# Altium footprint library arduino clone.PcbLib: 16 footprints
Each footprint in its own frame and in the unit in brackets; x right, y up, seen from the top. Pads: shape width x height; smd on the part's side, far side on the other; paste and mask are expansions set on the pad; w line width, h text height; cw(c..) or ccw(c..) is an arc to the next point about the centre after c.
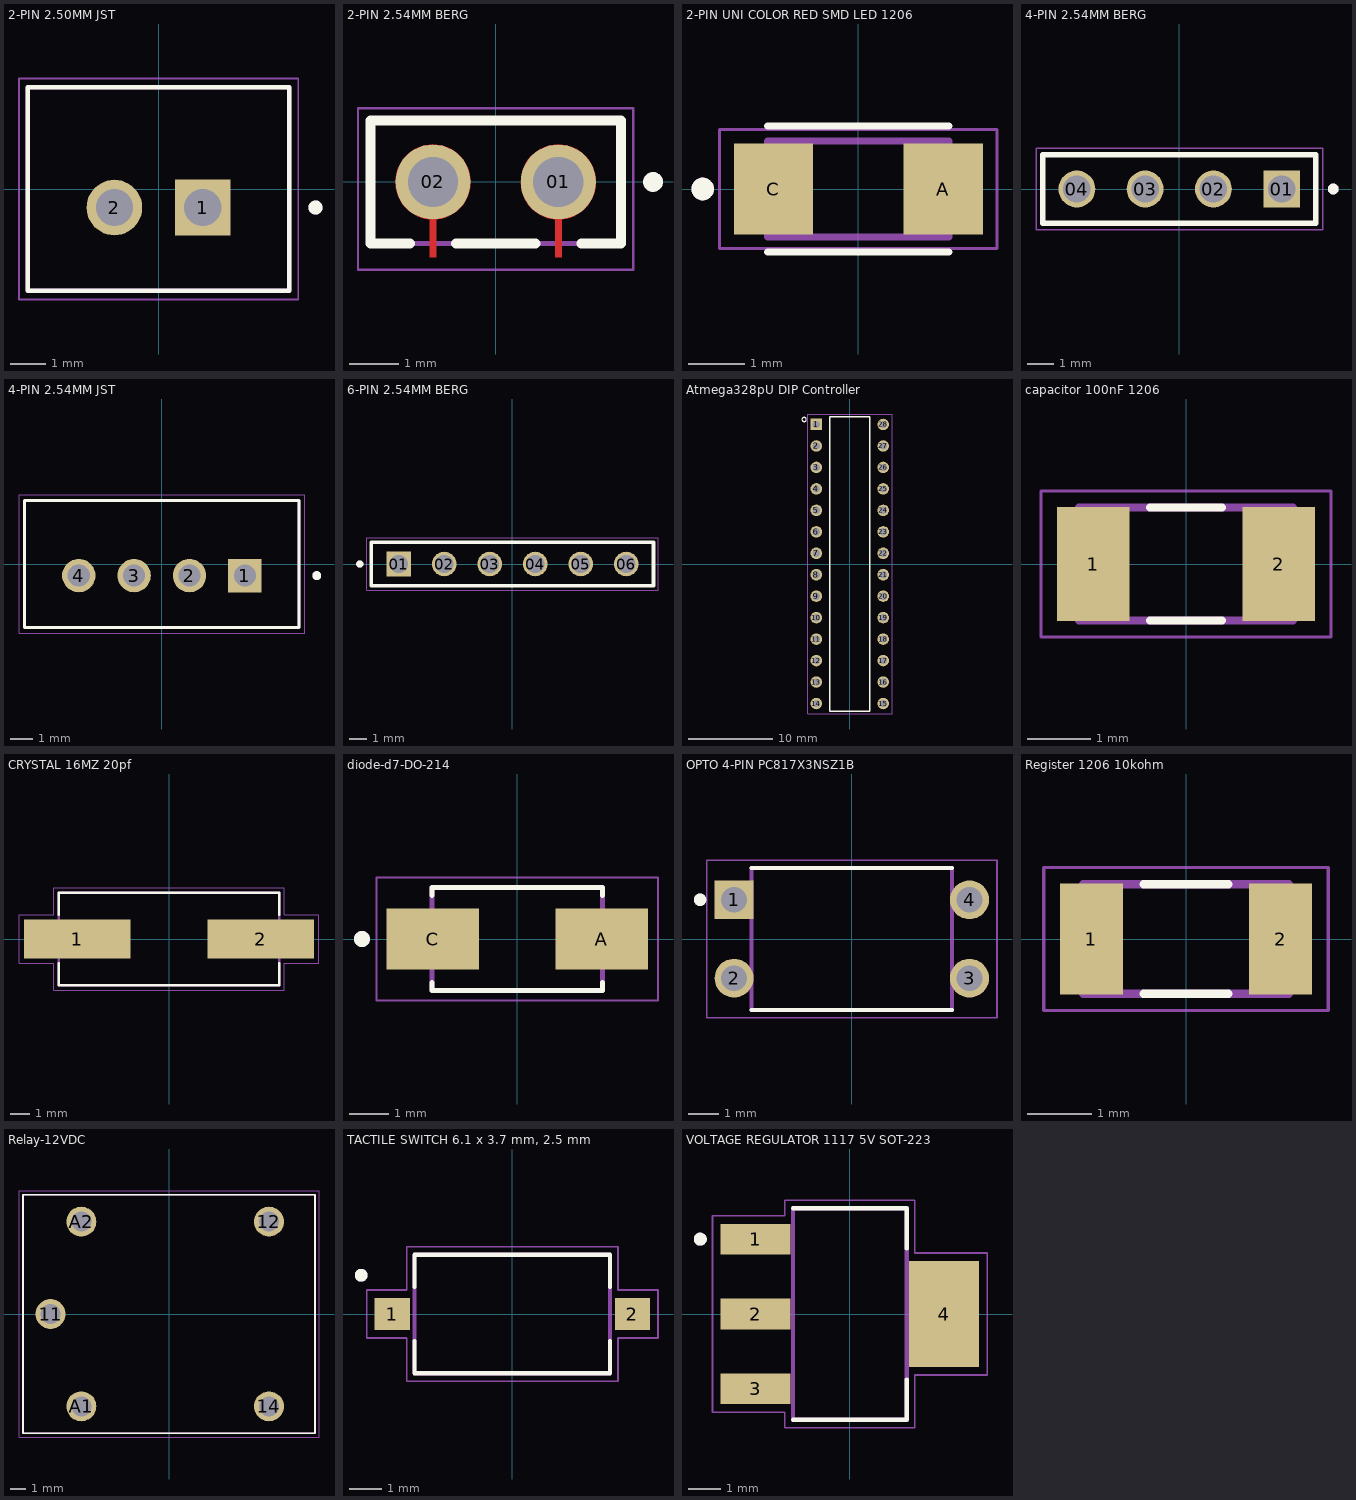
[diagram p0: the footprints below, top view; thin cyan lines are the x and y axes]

## 2-PIN 2.50MM JST [mm]
height 7
pads (2):
  rect 1.575x1.575 / inner round 1.575 / far side rect 1.575x1.575 hole 1.05: 1(1.25,-0.525)
  round 1.575 hole 1.05: 2(-1.25,-0.525)
Top Layer:
  text "OPTO 4-PIN PC817X3NSZ1B" at -7.874,-4.826 h1.52
Top Overlay:
  circle w0.2: c4.44,-0.525 r0.1
  lines w0.127: -3.7,-2.875 3.7,-2.875 3.7,2.875 -3.7,2.875 -3.7,-2.875
Mechanical 13:
  circle w0.2: c4.44,-0.525 r0.1
  lines w0.127: -3.7,-2.875 3.7,-2.875 3.7,2.875 -3.7,2.875 -3.7,-2.875
Mechanical 15:
  lines w0.05: -3.95,-3.125 -3.95,3.125 3.95,3.125 3.95,-3.125 -3.95,-3.125
3D body "step_temp.STEP": height 7, standoff -3.4, extent -3.7,-2.875 3.7,2.875

## 2-PIN 2.54MM BERG [mm] "SAMTEC_MTLW-102-08-L-S-300"
pads (2):
  round 1.52 hole 1.02: 01(1.27,0) 02(-1.27,0)
Top Layer:
  region: -1.191,0.756 -1.112,0.743 -1.035,0.723 -0.961,0.694 -0.89,0.658 -0.823,0.615 -0.761,0.565 -0.705,0.509 -0.655,0.447 -0.612,0.38 -0.576,0.309 -0.547,0.235 -0.527,0.158 -0.514,0.079 -0.51,0 -0.511,-0.038 -0.514,-0.076 -0.518,-0.113 -0.525,-0.151 -0.533,-0.187 -0.543,-0.224 -0.555,-0.259 -0.569,-0.294 -0.584,-0.329 -0.601,-0.363 -0.62,-0.395 -0.64,-0.427 -0.662,-0.458 -0.685,-0.487 -0.71,-0.516 -0.736,-0.543 -0.764,-0.569 -0.793,-0.593 -0.822,-0.616 -0.853,-0.638 -0.885,-0.658 -0.918,-0.676 -0.952,-0.692 -0.987,-0.707 -1.022,-0.721 -1.058,-0.732 -1.094,-0.742 -1.131,-0.75 -1.168,-0.756 -1.205,-0.76 -1.205,-1.53 -1.335,-1.53 -1.335,-0.76 -1.372,-0.756 -1.409,-0.75 -1.446,-0.742 -1.482,-0.732 -1.518,-0.721 -1.553,-0.707 -1.588,-0.692 -1.622,-0.676 -1.655,-0.658 -1.687,-0.638 -1.718,-0.616 -1.747,-0.593 -1.776,-0.569 -1.804,-0.543 -1.83,-0.516 -1.855,-0.487 -1.878,-0.458 -1.9,-0.427 -1.92,-0.395 -1.939,-0.363 -1.956,-0.329 -1.971,-0.294 -1.985,-0.259 -1.997,-0.224 -2.007,-0.187 -2.015,-0.151 -2.022,-0.113 -2.026,-0.076 -2.029,-0.038 -2.03,0 -2.026,0.079 -2.013,0.158 -1.993,0.235 -1.964,0.309 -1.928,0.38 -1.885,0.447 -1.835,0.509 -1.779,0.565 -1.717,0.615 -1.65,0.658 -1.579,0.694 -1.505,0.723 -1.428,0.743 -1.349,0.756 -1.27,0.76
  region: 1.349,0.756 1.428,0.743 1.505,0.723 1.579,0.694 1.65,0.658 1.717,0.615 1.779,0.565 1.835,0.509 1.885,0.447 1.928,0.38 1.964,0.309 1.993,0.235 2.013,0.158 2.026,0.079 2.03,0 2.029,-0.038 2.026,-0.076 2.022,-0.113 2.015,-0.151 2.007,-0.187 1.997,-0.224 1.985,-0.259 1.971,-0.294 1.956,-0.329 1.939,-0.363 1.92,-0.395 1.9,-0.427 1.878,-0.458 1.855,-0.487 1.83,-0.516 1.804,-0.543 1.776,-0.569 1.747,-0.593 1.718,-0.616 1.687,-0.638 1.655,-0.658 1.622,-0.676 1.588,-0.692 1.553,-0.707 1.518,-0.721 1.482,-0.732 1.446,-0.742 1.409,-0.75 1.372,-0.756 1.335,-0.76 1.335,-1.53 1.205,-1.53 1.205,-0.76 1.168,-0.756 1.131,-0.75 1.094,-0.742 1.058,-0.732 1.022,-0.721 0.987,-0.707 0.952,-0.692 0.918,-0.676 0.885,-0.658 0.853,-0.638 0.822,-0.616 0.793,-0.593 0.764,-0.569 0.736,-0.543 0.71,-0.516 0.685,-0.487 0.662,-0.458 0.64,-0.427 0.62,-0.395 0.601,-0.363 0.584,-0.329 0.569,-0.294 0.555,-0.259 0.543,-0.224 0.533,-0.187 0.525,-0.151 0.518,-0.113 0.514,-0.076 0.511,-0.038 0.51,0 0.514,0.079 0.527,0.158 0.547,0.235 0.576,0.309 0.612,0.38 0.655,0.447 0.705,0.509 0.761,0.565 0.823,0.615 0.89,0.658 0.961,0.694 1.035,0.723 1.112,0.743 1.191,0.756 1.27,0.76
Top Overlay:
  circle w0.2: c3.19,0 r0.1
  lines w0.2: -1.735,-1.245 -2.54,-1.245 -2.54,1.245 2.54,1.245 2.54,-1.245 1.735,-1.245 ; -0.805,-1.245 0.805,-1.245
Top Paste:
  region: -0.19,-0.455 -0.65,-0.455 -1.015,-0.77 -1.015,-1.53 -1.525,-1.53 -1.525,-0.77 -1.89,-0.455 -2.35,-0.455 -2.35,1.085 -0.19,1.085
  region: 2.35,-0.455 1.89,-0.455 1.525,-0.77 1.525,-1.53 1.015,-1.53 1.015,-0.77 0.65,-0.455 0.19,-0.455 0.19,1.085 2.35,1.085
Top Solder:
  drawing of 2 lines, arcs and shapes, not listed
Mechanical 13:
  circle w0.2: c3.19,0 r0.1
  lines w0.1: -2.54,-1.245 2.54,-1.245 2.54,1.245 -2.54,1.245 -2.54,-1.245
Mechanical 15:
  lines w0.05: -2.79,-1.78 2.79,-1.78 2.79,1.495 -2.79,1.495 -2.79,-1.78

## 2-PIN UNI COLOR RED SMD LED 1206 [mm] "LED_BR1102W-TR"
pads (2):
  rect 1.4x1.6 smd: A(1.5,0) C(-1.5,0)
Top Overlay:
  circle w0.2: c-2.75,0 r0.1
  lines w0.127: -1.6,-1.114 1.6,-1.114 ; -1.6,1.114 1.6,1.114
Mechanical 13:
  circle w0.2: c-2.75,0 r0.1
  lines w0.127: -1.6,-0.85 1.6,-0.85 1.6,0.85 -1.6,0.85 -1.6,-0.85
Mechanical 15:
  lines w0.05: -2.45,-1.05 2.45,-1.05 2.45,1.05 -2.45,1.05 -2.45,-1.05

## 4-PIN 2.54MM BERG [mm] "SAMTEC_MTSW-104-22-S-S-415"
pads (4):
  rect 1.37x1.37 / inner round 1.37 / far side rect 1.37x1.37 hole 1.02: 01(3.81,0)
  round 1.37 hole 1.02: 02(1.27,0) 03(-1.27,0) 04(-3.81,0)
Top Overlay:
  circle w0.2: c5.73,0 r0.1
  lines w0.2: -5.08,-1.27 -5.08,1.27 5.08,1.27 5.08,-1.27 -5.08,-1.27
Mechanical 13:
  circle w0.2: c5.73,0 r0.1
  lines w0.1: -5.08,-1.27 -5.08,1.27 ; -5.08,-1.27 5.08,-1.27 ; -5.08,-1.27 -5.08,1.27 ; -5.08,1.27 5.08,1.27 ; -5.08,1.27 5.08,1.27 ; 5.08,-1.27 5.08,1.27 ; 5.08,-1.27 5.08,1.27
Mechanical 15:
  lines w0.05: -5.33,-1.52 -5.33,1.52 5.33,1.52 5.33,-1.52 -5.33,-1.52

## 4-PIN 2.54MM JST [mm] "JST_B4B-XH-A"
height 7
pads (4):
  rect 1.508x1.508 / inner round 1.508 / far side rect 1.508x1.508 hole 1: 1(3.75,-0.525)
  round 1.508 hole 1: 2(1.25,-0.525) 3(-1.25,-0.525) 4(-3.75,-0.525)
Top Overlay:
  circle w0.2: c7,-0.525 r0.1
  lines w0.127: -6.2,-2.875 6.2,-2.875 6.2,2.875 -6.2,2.875 -6.2,-2.875
Mechanical 13:
  circle w0.2: c7,-0.525 r0.1
  lines w0.127: -6.2,-2.875 6.2,-2.875 6.2,2.875 -6.2,2.875 -6.2,-2.875
Mechanical 15:
  lines w0.05: -6.45,-3.125 6.45,-3.125 6.45,3.125 -6.45,3.125 -6.45,-3.125
3D body "step_temp.STEP": height 7, standoff -3.4, extent -6.2,-2.875 6.2,2.875

## 6-PIN 2.54MM BERG [mm] "berg-connector-6pin-2.54mm"
pads (6):
  rect 1.37x1.37 / inner round 1.37 / far side rect 1.37x1.37 hole 1.02: 01(-6.35,0)
  round 1.37 hole 1.02: 02(-3.81,0) 03(-1.27,0) 04(1.27,0) 05(3.81,0) 06(6.35,0)
Top Overlay:
  circle w0.2: c-8.525,0 r0.1
  lines w0.2: -7.875,-1.205 7.875,-1.205 7.875,1.205 -7.875,1.205 -7.875,-1.205
Mechanical 13:
  circle w0.2: c-8.525,0 r0.1
  lines w0.1: -7.875,-1.205 -7.875,1.205 ; -7.875,-1.205 7.875,-1.205 ; -7.875,-1.205 -7.875,1.205 ; -7.875,1.205 7.875,1.205 ; -7.875,1.205 7.875,1.205 ; 7.875,-1.205 7.875,1.205 ; 7.875,-1.205 7.875,1.205
Mechanical 15:
  lines w0.05: -8.125,-1.455 8.125,-1.455 8.125,1.455 -8.125,1.455 -8.125,-1.455

## Atmega328pU DIP Controller [mm] "Atmega328pU DIP"
pads (28):
  rect 1.358x1.358 hole 0.85: 1(-3.96,16.51)
  round 1.358 hole 0.85: 2(-3.96,13.97) 3(-3.96,11.43) 4(-3.96,8.89) 5(-3.96,6.35) 6(-3.96,3.81) 7(-3.96,1.27) 8(-3.96,-1.27) 9(-3.96,-3.81) 10(-3.96,-6.35) 11(-3.96,-8.89) 12(-3.96,-11.43) 13(-3.96,-13.97) 14(-3.96,-16.51) 15(3.96,-16.51) 16(3.96,-13.97) 17(3.96,-11.43) 18(3.96,-8.89) 19(3.96,-6.35) 20(3.96,-3.81) 21(3.96,-1.27) 22(3.96,1.27) 23(3.96,3.81) 24(3.96,6.35) 25(3.96,8.89) 26(3.96,11.43) 27(3.96,13.97) 28(3.96,16.51)
Top Overlay:
  circle w0: c-5.4,17.1 r0.254
  lines w0.152: -2.38,-17.4 -2.38,17.4 2.38,17.4 2.38,-17.4 -2.38,-17.4
Mechanical 15:
  lines w0.05: -5,-17.75 5,-17.75 5,17.75 -5,17.75 -5,-17.75

## capacitor 100nF 1206 [mm] "capacitor 100nF 1206"
pads (2):
  rect 1.16x1.82 smd: 1(-1.475,0) 2(1.475,0)
Top Overlay:
  lines w0.127: -0.57,-0.9 0.57,-0.9 ; -0.57,0.9 0.57,0.9
Mechanical 13:
  lines w0.127: -1.7,-0.9 -1.7,0.9 1.7,0.9 1.7,-0.9 -1.7,-0.9
Mechanical 15:
  lines w0.05: -2.308,-1.158 -2.308,1.158 2.308,1.158 2.308,-1.158 -2.308,-1.158

## CRYSTAL 16MZ 20pf [mm] "XTAL_ECS-160-20-5PX-TR"
pads (2):
  rect 5.5x2 smd: 1(-4.75,0) 2(4.75,0)
Top Overlay:
  lines w0.127: -5.7,-1.254 -5.7,-2.4 5.7,-2.4 5.7,-1.254 ; -5.7,1.254 -5.7,2.4 5.7,2.4 5.7,1.254
Mechanical 13:
  lines w0.127: -5.7,-2.4 -5.7,2.4 5.7,2.4 5.7,-2.4 -5.7,-2.4
Mechanical 15:
  lines w0.05: -7.75,-1.25 -5.95,-1.25 -5.95,-2.65 5.95,-2.65 5.95,-1.25 7.75,-1.25 7.75,1.25 5.95,1.25 5.95,2.65 -5.95,2.65 -5.95,1.25 -7.75,1.25 -7.75,-1.25
3D body "step_temp.STEP": height 3.2, standoff 0, extent -6.6,-2.4 6.6,2.4

## diode-d7-DO-214 [mm] "diode-d7-DO-214"
height 2.4
pads (2):
  rect 2.33x1.55 smd: A(2.135,0) C(-2.135,0)
Top Overlay:
  circle w0.2: c-3.919,0 r0.1
  lines w0.127: -2.15,-1.095 -2.15,-1.302 2.15,-1.302 2.15,-1.095 ; -2.15,1.095 -2.15,1.302 2.15,1.302 2.15,1.095
Mechanical 13:
  circle w0.2: c-3.919,0 r0.1
  lines w0.127: -2.15,-1.302 -2.15,1.302 2.15,1.302 2.15,-1.302 -2.15,-1.302
Mechanical 15:
  lines w0.05: -3.55,-1.552 -3.55,1.552 3.55,1.552 3.55,-1.552 -3.55,-1.552
3D body "step_temp.STEP": height 2.4, standoff 0, extent -2.598,-1.302 2.598,1.302

## OPTO 4-PIN PC817X3NSZ1B [mm] "DIP762W50P254L495H455Q4"
height 4.55
pads (4):
  rect 1.26x1.26 / inner round 1.26 / far side rect 1.26x1.26 hole 0.84: 1(-3.81,1.27)
  round 1.26 hole 0.84: 2(-3.81,-1.27) 3(3.81,-1.27) 4(3.81,1.27)
Top Overlay:
  circle w0.2: c-4.91,1.27 r0.1
  lines w0.127: -3.25,-2.3 3.25,-2.3 ; -3.25,2.3 3.25,2.3
Mechanical 13:
  circle w0.2: c-4.91,1.27 r0.1
  lines w0.127: -3.25,-2.3 -3.25,2.3 3.25,2.3 3.25,-2.3 -3.25,-2.3
Mechanical 15:
  lines w0.05: -4.7,-2.55 -4.7,2.55 4.7,2.55 4.7,-2.55 -4.7,-2.55
3D body "step_temp.STEP": height 4.55, standoff -3.6, extent -3.935,-2.3 3.935,2.3

## PCBComponent_1 [mm]

## Register 1206 10kohm [mm] "Register RESC3015X65N"
pads (2):
  rect 0.98x1.72 smd: 1(-1.47,0) 2(1.47,0)
Top Overlay:
  lines w0.127: -0.66,-0.85 0.66,-0.85 ; -0.66,0.85 0.66,0.85
Mechanical 13:
  lines w0.127: -1.6,-0.85 1.6,-0.85 1.6,0.85 -1.6,0.85 -1.6,-0.85
Mechanical 15:
  lines w0.05: -2.21,-1.11 2.21,-1.11 2.21,1.11 -2.21,1.11 -2.21,-1.11

## Relay-12VDC [mm] "RELAY_833H-1C-S-12VDC"
height 15.5
pads (5):
  round 1.95 hole 1.3: 11(-7.7,0) 12(6.5,6) 14(6.5,-6) A1(-5.7,-6) A2(-5.7,6)
Top Overlay:
  lines w0.127: -9.5,-7.75 -9.5,7.75 9.5,7.75 9.5,-7.75 -9.5,-7.75
Mechanical 13:
  lines w0.127: -9.5,-7.75 -9.5,7.75 9.5,7.75 9.5,-7.75 -9.5,-7.75
Mechanical 15:
  lines w0.05: -9.75,-8 -9.75,8 9.75,8 9.75,-8 -9.75,-8

## TACTILE SWITCH 6.1 x 3.7 mm, 2.5 mm [mm] "PUSHBUTTON_SMD_6.1 x 3.7 mm, 2.5 mm"
height 2.5
pads (2):
  rect 1.1x1 smd: 1(-3.75,0) 2(3.75,0)
Top Overlay:
  circle w0.2: c-4.72,1.21 r0.1
  lines w0.127: -3.05,-0.85 -3.05,-1.85 3.05,-1.85 3.05,-0.85 ; -3.05,0.85 -3.05,1.85 3.05,1.85 3.05,0.85
Mechanical 13:
  circle w0.2: c-4.72,1.21 r0.1
  lines w0.127: -3.05,-1.85 -3.05,1.85 3.05,1.85 3.05,-1.85 -3.05,-1.85
Mechanical 15:
  lines w0.05: -4.55,-0.75 -3.3,-0.75 -3.3,-2.1 3.3,-2.1 3.3,-0.75 4.55,-0.75 4.55,0.75 3.3,0.75 3.3,2.1 -3.3,2.1 -3.3,0.75 -4.55,0.75 -4.55,-0.75
3D body "step_temp.STEP": height 2.5, standoff -0.05, extent -4.05,-1.85 4.05,1.85

## VOLTAGE REGULATOR 1117 5V SOT-223 [mm] "SOT230P700X180-4N"
pads (4):
  rect 2.15x0.95 smd: 1(-2.9,2.3) 2(-2.9,0) 3(-2.9,-2.3)
  rect 2.15x3.25 smd: 4(2.9,0)
Top Overlay:
  circle w0.2: c-4.6,2.3 r0.1
  lines w0.127: -1.75,-3.25 1.75,-3.25 1.75,-2.01 ; -1.75,3.25 1.75,3.25 1.75,2.01
Mechanical 13:
  circle w0.2: c-4.6,2.3 r0.1
  lines w0.127: -1.75,-3.25 1.75,-3.25 1.75,3.25 -1.75,3.25 -1.75,-3.25
Mechanical 15:
  lines w0.05: -4.225,-3.025 -2,-3.025 -2,-3.5 2,-3.5 2,-1.875 4.225,-1.875 4.225,1.875 2,1.875 2,3.5 -2,3.5 -2,3.025 -4.225,3.025 -4.225,-3.025
3D body "step_temp.STEP": height 1.8, standoff 0, extent -3.499,-3.25 3.499,3.25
